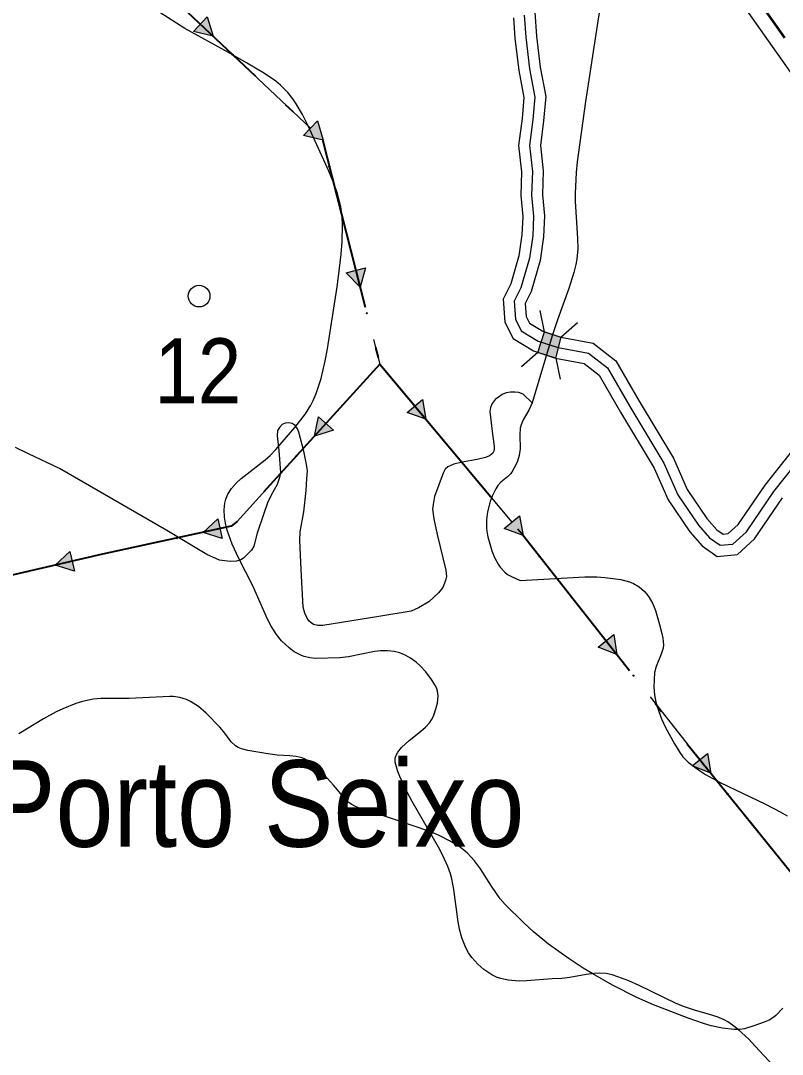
# Model space of a CAD drawing. Extents: x -64005 to -55000, y -89025 to -80000.
# Drawn here: x -59747 to -59043, y -83126 to -82170 of the extents above; entities that cross this region are included whole.
import ezdxf
from ezdxf.enums import TextEntityAlignment as Align

# ---------------------------------------------------------------- set-up
doc = ezdxf.new("R2010")
doc.units = 0
doc.header["$LTSCALE"] = 32
for name, pattern in [('DASH_DOUBLE_DOT', [9.2, 5, -1.2, 0.3, -1.2, 0.3, -1.2]), ('DOT_DASHED', [7.7, 5, -1.2, 0.3, -1.2]), ('LONG_DASHED', [7.5, 6, -1.5])]:
    doc.linetypes.add(name, pattern=pattern)
for name, color, linetype, lineweight in [('18', 7, 'Continuous', 25), ('2', 7, 'Continuous', 25), ('20', 7, 'Continuous', 25), ('24', 7, 'Continuous', 25), ('39', 7, 'LONG_DASHED', 25), ('52', 7, 'Continuous', 25), ('63', 7, 'DASH_DOUBLE_DOT', 25), ('7', 7, 'Continuous', 13), ('8', 7, 'Continuous', 25)]:
    doc.layers.add(name, color=color, linetype=linetype, lineweight=lineweight)
doc.layers.add('38', color=7, linetype='Continuous')
doc.layers.add('45', color=7, linetype='Continuous')

msp = doc.modelspace()

# ---------------------------------------------------------------- hatches: boundary and pattern name
at = {"layer": '18'}
for points in [[(-59574.5, -82166.78), (-59569.22, -82184.51), (-59587.21, -82180.23)], [(-59472.77, -82262.96), (-59467.48, -82280.69), (-59485.48, -82276.4)], [(-59428.22, -82398.75), (-59433.21, -82416.56), (-59446.14, -82403.33)], [(-59375.58, -82520.59), (-59372.4, -82538.81), (-59389.77, -82532.45)], [(-59457.85, -82548.86), (-59475.46, -82554.51), (-59471.55, -82536.43)], [(-59560.74, -82649.04), (-59578.36, -82643.41), (-59564.68, -82630.97)], [(-59285.81, -82628.02), (-59282.63, -82646.24), (-59300, -82639.88)], [(-59697.35, -82679.13), (-59715.04, -82673.72), (-59701.51, -82661.11)], [(-59198.69, -82737.95), (-59196.04, -82756.25), (-59213.22, -82749.39)], [(-59112, -82847.72), (-59109.12, -82866), (-59126.38, -82859.35)]]:
    msp.add_hatch(color=256, dxfattribs=at).paths.add_polyline_path(points)
at = {"layer": '63'}
msp.add_hatch(color=256, dxfattribs=at).paths.add_polyline_path([(-59262.73, -82457.93), (-59247.58, -82462.88), (-59252.5, -82482.32), (-59268.95, -82476.94)])

# ---------------------------------------------------------------- linework, layer by layer
at = {"layer": '18'}
for p, q in [((-59634.62, -82122.68), (-59580.86, -82173.5)), ((-59532.88, -82218.86), (-59479.12, -82269.68)), ((-59455.49, -82329.36), (-59437.18, -82401.04)), ((-59415, -82487.84), (-59464.7, -82542.64)), ((-59340.34, -82577.18), (-59292.9, -82633.95)), ((-59251.72, -82685.54), (-59205.95, -82743.67)), ((-59077.68, -82904.88), (-59031.16, -82962.4))]:
    msp.add_line(p, q, dxfattribs=at)
at = {"layer": '18', "linetype": 'DOT_DASHED', "lineweight": 40}
for points in [[(-60219.71, -81521.05), (-59978.44, -81794.82), (-59646.58, -82111.37), (-59468.07, -82280.13), (-59415, -82487.84), (-59283.25, -82645.5), (-59128.86, -82841.58), (-58714.75, -83353.72), (-58581.73, -83517.45), (-58506.34, -83610.82), (-58347.94, -83807.01), (-58247.59, -83933.66), (-58191.9, -84001.28), (-58164.58, -84034.46), (-58137.14, -84068.11), (-57960.33, -84286.53), (-57797.76, -84487.35), (-57624.25, -84702.51), (-57366.28, -84880.22), (-57249.59, -84960.27), (-57114.47, -85053.89), (-56518.68, -85641.19), (-56404.54, -85755.57)], [(-59415, -82487.84), (-59547.04, -82633.44), (-59552.52, -82637.79), (-59671.25, -82663.61), (-59990.81, -82737.41), (-60092.11, -82765.4), (-60184.07, -82781.9), (-60369.54, -82824.5), (-60744.45, -82882.06)]]:
    msp.add_lwpolyline(points, dxfattribs=at)
at = {"layer": '18'}
for points in [[(-59574.5, -82166.78), (-59569.22, -82184.51), (-59587.21, -82180.23)], [(-59472.77, -82262.96), (-59467.48, -82280.69), (-59485.48, -82276.4)], [(-59428.22, -82398.75), (-59433.21, -82416.56), (-59446.14, -82403.33)], [(-59375.58, -82520.59), (-59372.4, -82538.81), (-59389.77, -82532.45)], [(-59457.85, -82548.86), (-59475.46, -82554.51), (-59471.55, -82536.43)], [(-59560.74, -82649.04), (-59578.36, -82643.41), (-59564.68, -82630.97)], [(-59285.81, -82628.02), (-59282.63, -82646.24), (-59300, -82639.88)], [(-59697.35, -82679.13), (-59715.04, -82673.72), (-59701.51, -82661.11)], [(-59198.69, -82737.95), (-59196.04, -82756.25), (-59213.22, -82749.39)], [(-59112, -82847.72), (-59109.12, -82866), (-59126.38, -82859.35)]]:
    msp.add_lwpolyline(points, close=True, dxfattribs=at)
for points in [[(-59420.84, -82465), (-59415, -82487.84), (-59382.68, -82526.52)], [(-59509.05, -82591.55), (-59547.04, -82633.44), (-59552.52, -82637.79), (-59562.71, -82640.01)], [(-59627.22, -82654.04), (-59671.25, -82663.61), (-59699.43, -82670.12)], [(-59165.11, -82795.54), (-59128.86, -82841.58), (-59119.19, -82853.54)]]:
    msp.add_lwpolyline(points, dxfattribs=at)
for centre in [(-59551.05, -82201.68), (-59461.68, -82305.14), (-59427.02, -82440.78), (-59356.37, -82557.99), (-59492.25, -82573.03), (-59602.79, -82648.72), (-59267.19, -82665.9), (-59739.4, -82679.35), (-59180.58, -82775.89), (-59093.4, -82885.43)]:
    msp.add_circle(centre, 0.5, dxfattribs=at)
at = {"layer": '2', "lineweight": 53}
msp.add_lwpolyline([(-59040.72, -82186.24), (-59099.13, -82102.89)], dxfattribs=at)
at = {"layer": '20'}
for p, q in [((-59262.73, -82457.94), (-59266.81, -82438.19)), ((-59247.52, -82462.89), (-59232.4, -82449.2)), ((-59268.95, -82476.94), (-59283.89, -82490.47)), ((-59252.28, -82482.36), (-59248.27, -82501.81))]:
    msp.add_line(p, q, dxfattribs=at)
at = {"layer": '24'}
for points in [[(-59545.91, -81746.47), (-59529.98, -81743.74), (-59504.13, -81745.26), (-59451.67, -81790.89), (-59429.61, -81841.85), (-59391.59, -81872.65), (-59304.15, -81914.47), (-59242.56, -81940.33), (-59198.46, -81992.8), (-59131.54, -82081.79), (-59021.28, -82238.07)], [(-59521.68, -82219.25), (-59538.2, -82209.12), (-59554.9, -82199.58), (-59595.21, -82177.35), (-59633.77, -82152.79)], [(-59318.96, -83047.66), (-59324.5, -83042.78), (-59329.93, -83036.54), (-59332.9, -83032.18), (-59335.4, -83027.67), (-59339.21, -83018.3), (-59341.41, -83010.2), (-59342.69, -83003.6), (-59346.57, -82973.56), (-59348.42, -82963.86), (-59349.68, -82959.14), (-59352.12, -82952.29), (-59357, -82941.68), (-59360.66, -82934.6), (-59385.02, -82892.23), (-59390.02, -82882.9), (-59396.5, -82869.01), (-59398.29, -82864.41), (-59400.96, -82855.74), (-59400.83, -82852.24), (-59399.67, -82848.84), (-59398.4, -82846.63), (-59394.88, -82842.31), (-59387.91, -82835.99), (-59377.51, -82827.64), (-59372.71, -82823.4), (-59368.7, -82819.05), (-59367.11, -82816.82), (-59365.38, -82813.4), (-59362.8, -82805.6), (-59361.8, -82801.27), (-59361.2, -82794.63), (-59361.67, -82790.3), (-59362.25, -82788.21), (-59363.6, -82785.23), (-59367.29, -82779.34), (-59372.5, -82772.4), (-59377.74, -82766.74), (-59381.51, -82763.37), (-59386.54, -82759.7), (-59390.81, -82757.26), (-59396.45, -82754.91), (-59401.8, -82753.54), (-59407.82, -82752.89), (-59414.51, -82753.04), (-59419.87, -82753.66), (-59443.96, -82758.42), (-59452, -82759.39), (-59474.36, -82759.95), (-59479.6, -82759.46), (-59484.84, -82758.25), (-59487.45, -82757.3), (-59494.04, -82753.74), (-59498.91, -82750.23), (-59505.83, -82743.7), (-59510.44, -82737.97), (-59515.32, -82730.27), (-59518.7, -82723.78), (-59532.39, -82692.94), (-59545.38, -82667.52), (-59551.43, -82654.33), (-59556.12, -82641.24), (-59557.71, -82634.82), (-59558.58, -82629.23), (-59558.86, -82622.43), (-59558.23, -82616.54), (-59557.3, -82612.74), (-59555.5, -82608.18), (-59552.27, -82602.89), (-59547.61, -82597.5), (-59543.26, -82593.46), (-59521.04, -82576.24), (-59516.42, -82572.17), (-59511.28, -82566.71), (-59493.63, -82546.37), (-59483.85, -82533.82), (-59478.77, -82525.76), (-59476.55, -82521.52), (-59473.7, -82514.88), (-59469.3, -82501.25), (-59465.39, -82484.76), (-59463.35, -82473.7), (-59454.47, -82416.3), (-59452.75, -82404.3), (-59450.69, -82386.31), (-59449.79, -82374.33), (-59449.39, -82359.39), (-59449.82, -82351.32), (-59451.14, -82342.46), (-59452.76, -82335.44), (-59454.26, -82330.21), (-59457.87, -82319.82), (-59462.09, -82309.5), (-59481.31, -82267.43), (-59486.52, -82257), (-59492.3, -82247.11), (-59495.5, -82242.44), (-59500.16, -82236.57), (-59506.74, -82229.9), (-59511.15, -82226.31), (-59521.68, -82219.25)], [(-59047.05, -83140.92), (-59067.89, -83118.41), (-59073.99, -83112.13), (-59083.69, -83103.16), (-59088.87, -83098.95), (-59093.39, -83095.91), (-59096.55, -83094.2), (-59103.17, -83091.39), (-59110.07, -83089.17), (-59124.13, -83085.33), (-59134.38, -83081.89), (-59141.68, -83078.75), (-59175.15, -83062.52), (-59184.94, -83058.17), (-59195.03, -83054.31), (-59200.22, -83052.63), (-59205.73, -83051.43), (-59211.89, -83051.03), (-59216.84, -83051.27), (-59224.3, -83052.26), (-59239.25, -83054.96), (-59246.71, -83055.82), (-59255.53, -83056.07), (-59279.42, -83058.12), (-59286.23, -83058.33), (-59296.4, -83057.55), (-59303.14, -83056), (-59306.49, -83054.84), (-59311.5, -83052.54), (-59318.96, -83047.66)]]:
    msp.add_lwpolyline(points, dxfattribs=at)
at = {"layer": '39'}
msp.add_lwpolyline([(-59281.6, -82165.07), (-59280.08, -82185.59), (-59276.66, -82214.84), (-59271.72, -82240.86), (-59273.61, -82261.75), (-59276.65, -82285.69), (-59273.99, -82309.62), (-59274.74, -82331.66), (-59272.84, -82351.03), (-59273.6, -82369.27), (-59276.64, -82389.78), (-59284.61, -82417.14), (-59290.68, -82429.67), (-59289.54, -82446.39), (-59284.22, -82457.03), (-59268.65, -82466.52), (-59250.04, -82472.6), (-59221.94, -82477.73), (-59204.47, -82491.4), (-59183.96, -82527.11), (-59152.43, -82579.53), (-59139.51, -82608.59), (-59120.51, -82636.7), (-59110.26, -82648.47), (-59100.39, -82655.31), (-59088.61, -82654.17), (-59076.08, -82642.77), (-59050.64, -82605.54), (-59023.31, -82570.96)], dxfattribs=at)
at = {"layer": '52'}
msp.add_circle((-59582.08, -82424.93), 10, dxfattribs=at)
at = {"layer": '63'}
msp.add_lwpolyline([(-59262.73, -82457.93), (-59247.58, -82462.88), (-59252.5, -82482.32), (-59268.95, -82476.94)], close=True, dxfattribs=at)
at = {"layer": '7', "lineweight": 25}
for points in [[(-59196.61, -82064.96), (-59213.56, -82170.59), (-59224.85, -82244.92), (-59232.59, -82300.7), (-59233.48, -82310.51), (-59234.32, -82330.18), (-59234.41, -82337.45), (-59233.57, -82352.03), (-59232.13, -82371.47), (-59232.09, -82381.17), (-59232.98, -82390.83), (-59233.89, -82395.64), (-59235.77, -82403.21), (-59240.29, -82418.01), (-59250.66, -82446.96), (-59255.56, -82461.53), (-59274.15, -82523.48)], [(-59274.15, -82523.48), (-59282.47, -82515.75), (-59286.52, -82514.09), (-59289.83, -82513.72), (-59294.24, -82513.63), (-59298.2, -82514.27), (-59301.96, -82516.02), (-59305.36, -82518.41), (-59308.49, -82520.62), (-59311.25, -82524.3), (-59312.62, -82528.07), (-59313.18, -82531.74), (-59310.97, -82552.62), (-59309.21, -82563.63), (-59309.21, -82566.21), (-59309.67, -82568.23), (-59310.59, -82570.25), (-59313.53, -82572.65), (-59317.3, -82574.3), (-59325.11, -82575.96), (-59338.9, -82578.35), (-59346.62, -82580.28), (-59352.23, -82582.68), (-59354.71, -82584.88), (-59356.36, -82588.56), (-59364.54, -82610.17), (-59365.73, -82617.53), (-59366.28, -82621.85), (-59365, -82630.77), (-59361.87, -82645.3), (-59354.05, -82678.49), (-59353.41, -82684.28), (-59354.23, -82688.05), (-59356.8, -82694.22), (-59360.76, -82699.27), (-59369.58, -82707.73), (-59379.32, -82713.25), (-59386.12, -82716.19), (-59415.99, -82721.25), (-59467.74, -82729.53), (-59472.33, -82729.44), (-59476.38, -82728.61), (-59478.49, -82727.05), (-59480.51, -82725.12), (-59482.44, -82722.18), (-59484.47, -82718.04), (-59485.75, -82712.43), (-59487.67, -82677.67), (-59488.96, -82650.91), (-59488.68, -82642.91), (-59485.38, -82624.42), (-59483.07, -82604.75), (-59482.52, -82593.53), (-59481.97, -82586.54), (-59482.71, -82580.56), (-59485.38, -82568.42), (-59489.97, -82550.76), (-59491.17, -82547.63), (-59493.38, -82544.69), (-59496.13, -82542.85), (-59499.08, -82542.21), (-59502.57, -82542.57), (-59505.23, -82543.68), (-59507.81, -82546.44), (-59509.55, -82549.1), (-59509.92, -82554.16), (-59508.45, -82567.77), (-59506.79, -82588.1), (-59507.62, -82592.6), (-59510.01, -82599.23), (-59515.43, -82608.88), (-59518.83, -82616.24), (-59522.69, -82626.72), (-59528.29, -82644.2), (-59531.6, -82656.06), (-59533.72, -82659.92), (-59536.66, -82663.05), (-59541.07, -82667.28), (-59543.37, -82668.93), (-59547.5, -82670.13), (-59553.48, -82670.4), (-59563.13, -82669.03), (-59574.99, -82663.88), (-59611.85, -82641.81), (-59711.14, -82584.29), (-59739.82, -82570.68), (-59751.77, -82564.8)], [(-59274.15, -82523.48), (-59277.27, -82530.45), (-59282.37, -82539.37), (-59284.4, -82544.02), (-59285.19, -82547.02), (-59285.68, -82553.24), (-59285.29, -82566.02), (-59286.11, -82572.26), (-59287.84, -82577.6), (-59289.33, -82581.04), (-59292.94, -82587.66), (-59294.1, -82589.27), (-59296.95, -82592), (-59303.22, -82596.98), (-59305.83, -82600.06), (-59307.75, -82603.27), (-59311.05, -82610.04), (-59312.84, -82614.75), (-59315.36, -82624.43), (-59316.3, -82631.76), (-59316.37, -82638.99), (-59316.07, -82642.52), (-59315.18, -82647.65), (-59311.52, -82660.32), (-59308.88, -82666.71), (-59305.61, -82672.72), (-59303.71, -82675.47), (-59299.33, -82680.29), (-59296.83, -82682.28), (-59292.67, -82684.61), (-59285.26, -82687.81), (-59225.55, -82684.6), (-59214.41, -82684.53), (-59206.98, -82685), (-59192.14, -82686.94), (-59184.22, -82689.03), (-59180.47, -82690.66), (-59175.18, -82693.89), (-59170.39, -82698.12), (-59168.21, -82700.63), (-59166.08, -82703.56), (-59162.71, -82709.53), (-59160.22, -82715.66), (-59156.37, -82728.46), (-59154.16, -82736.94), (-59153.38, -82741.19), (-59152.87, -82747.49), (-59153.11, -82750.35), (-59154.77, -82756.02), (-59159.6, -82767.3), (-59160.95, -82772.99), (-59161.53, -82786.62), (-59161.06, -82793.56), (-59159.87, -82800.42), (-59158.95, -82803.78), (-59154.49, -82815.91), (-59150.96, -82823.67), (-59142.71, -82838.87), (-59137.71, -82847.09), (-59134.92, -82850.9), (-59129.89, -82855.98), (-59120.42, -82862.96), (-59113.86, -82867.17), (-59100.33, -82874.74), (-59058.52, -82894.62), (-59045.02, -82901.72), (-59038.49, -82905.61)], [(-59055.1, -83094.34), (-59059.7, -83096.29), (-59069.32, -83099.56), (-59077.85, -83102.35), (-59082.14, -83102.99), (-59087.43, -83103.03), (-59098.07, -83101.97), (-59108.74, -83099.67), (-59115.85, -83097.62), (-59129.98, -83092.73), (-59161.9, -83080.16), (-59177.29, -83073.33), (-59200.03, -83061.92), (-59218.12, -83051.66), (-59226.95, -83046.29), (-59239.95, -83037.87), (-59258.97, -83024.27), (-59273.05, -83012.66), (-59281.95, -83004.46), (-59299.13, -82987.47), (-59303.8, -82982.22), (-59311.89, -82970.66), (-59321.97, -82954.6), (-59327.53, -82946.98), (-59333.94, -82940.07), (-59337.58, -82936.97), (-59341.77, -82933.9), (-59350.49, -82928.47), (-59359.6, -82923.87), (-59365.83, -82921.17), (-59378.58, -82916.44), (-59414.46, -82904.46), (-59432.42, -82899.08), (-59438.17, -82896.61), (-59440.94, -82895.05), (-59443.21, -82893.46), (-59447.24, -82889.77), (-59454.28, -82881.38), (-59457.91, -82877.28), (-59471.83, -82861.72), (-59477.14, -82857.08), (-59480.13, -82855.03), (-59484.09, -82852.98), (-59486.82, -82851.96), (-59492.43, -82850.61), (-59498.2, -82849.91), (-59509.91, -82849.25), (-59518.57, -82848.2), (-59536.97, -82845.22), (-59542.97, -82843.46), (-59545.91, -82842.21), (-59548.39, -82840.76), (-59552.54, -82836.98), (-59559.35, -82827.75), (-59562.99, -82823.38), (-59575.63, -82810.62), (-59582.64, -82804.55), (-59589.91, -82799.83), (-59593.78, -82798.04), (-59599.82, -82796.12), (-59606, -82795.21), (-59609.12, -82795.15), (-59646.71, -82796.86), (-59657.82, -82796.92), (-59672.64, -82797.04), (-59680.04, -82797.72), (-59689.73, -82799.67), (-59696, -82801.55), (-59708.18, -82806.45), (-59714.12, -82809.35), (-59725.79, -82815.8), (-59748.81, -82829.62)], [(-59042.42, -83083.24), (-59048.82, -83090.15), (-59050.81, -83091.77), (-59055.1, -83094.34)]]:
    msp.add_lwpolyline(points, dxfattribs=at)
at = {"layer": '8'}
for points in [[(-59271.77, -82162.42), (-59270.12, -82184.64), (-59266.77, -82213.32), (-59261.63, -82240.37), (-59263.67, -82262.83), (-59266.58, -82285.77), (-59263.97, -82309.24), (-59264.72, -82331.34), (-59262.82, -82350.75), (-59263.63, -82370.21), (-59266.85, -82391.92), (-59275.24, -82420.74), (-59280.52, -82431.64), (-59279.7, -82443.71), (-59276.56, -82449.99), (-59264.44, -82457.38), (-59247.58, -82462.88), (-59217.72, -82468.34), (-59196.77, -82484.73), (-59175.34, -82522.04), (-59143.54, -82574.9), (-59130.73, -82603.72), (-59112.57, -82630.59), (-59103.54, -82640.96), (-59097.72, -82645)], [(-59103.08, -82665.61), (-59084.34, -82663.8), (-59068.48, -82649.38), (-59042.58, -82611.47)]]:
    msp.add_lwpolyline(points, dxfattribs=at)
at = {"layer": '8', "linetype": 'LONG_DASHED'}
for points in [[(-59291.43, -82167.72), (-59290.04, -82186.54), (-59286.55, -82216.36), (-59281.81, -82241.35), (-59283.55, -82260.67), (-59286.72, -82285.61), (-59284.01, -82310), (-59284.76, -82331.98), (-59282.86, -82351.31), (-59283.57, -82368.33), (-59286.43, -82387.64), (-59293.98, -82413.54), (-59300.84, -82427.7), (-59299.38, -82449.07), (-59291.88, -82464.07), (-59272.86, -82475.66), (-59252.5, -82482.32), (-59226.16, -82487.12), (-59212.17, -82498.07), (-59192.58, -82532.18), (-59161.32, -82584.16), (-59148.29, -82613.46), (-59128.45, -82642.81), (-59116.98, -82655.98), (-59103.08, -82665.61)], [(-59097.72, -82645), (-59092.88, -82644.54), (-59083.68, -82636.16), (-59058.7, -82599.61), (-59030.84, -82564.35)]]:
    msp.add_lwpolyline(points, dxfattribs=at)

# ---------------------------------------------------------------- texts
at = {"layer": '38', "width": 0.9}
msp.add_text('12', height=60, rotation=0.007, dxfattribs=at).set_placement((-59583.22, -82524.02), align=Align.CENTER)
at = {"layer": '45', "width": 0.9}
msp.add_text('Sobral do Porto Seixo', height=80, rotation=0.007, dxfattribs=at).set_placement((-59749.62, -82934.14), align=Align.CENTER)

doc.saveas('drawing.dxf')
